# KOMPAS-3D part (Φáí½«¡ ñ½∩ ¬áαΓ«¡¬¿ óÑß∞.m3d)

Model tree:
1. Эскиз:1
2. Операция выдавливания:1
     Толщина стенки 2 = 6; Расстояние 1 = 0.6
3. Эскиз:2
4. Операция выдавливания:2
     Толщина стенки 1 = 12; Толщина стенки 2 = 12; Расстояние 1 = 0.6; Расстояние 2 = 0.6
5. Эскиз:3
6. Операция выдавливания:3
     Толщина стенки 1 = 12; Толщина стенки 2 = 12; Расстояние 1 = 0.6; Расстояние 2 = 0.6
7. Эскиз:4
8. Операция выдавливания:4
     Толщина стенки 1 = 35; Толщина стенки 2 = 35; Расстояние 1 = 0.6; Расстояние 2 = 0.6
9. Эскиз:5
10. Вырезать элемент выдавливания:1
     Расстояние 1 = 10
